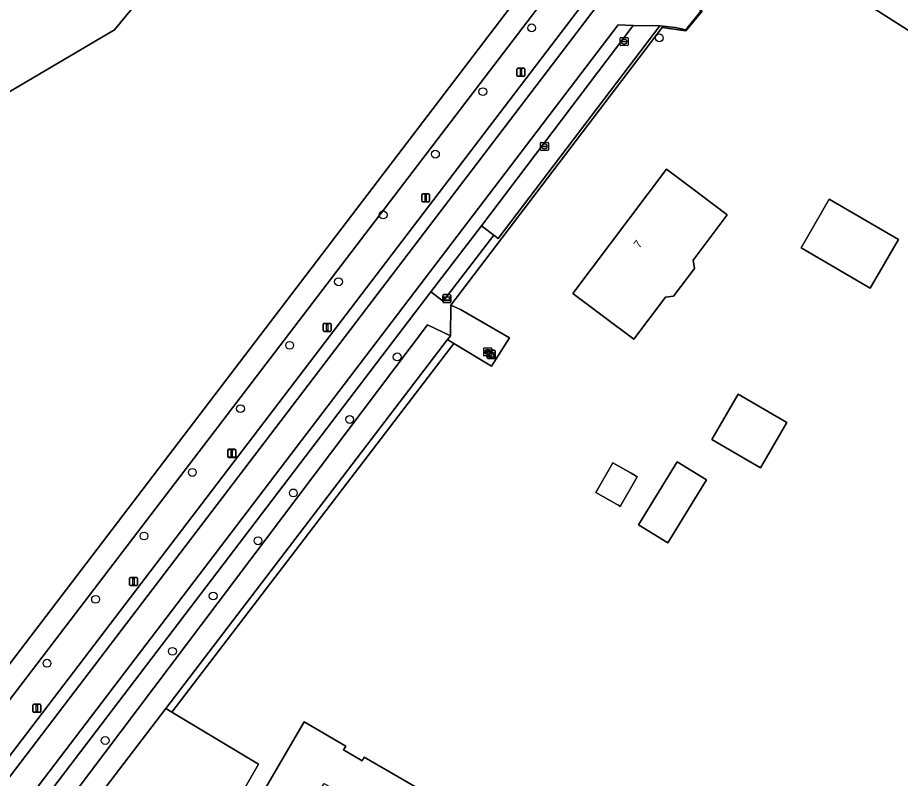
# Model space of a CAD drawing. Extents: x 156502 to 159075, y 384229 to 386100.
# Drawn here: x 157087.9 to 157198.2, y 385919.1 to 386014.1 of the extents above; entities that cross this region are included whole.
import ezdxf

# ---------------------------------------------------------------- set-up
doc = ezdxf.new("R2010")
doc.units = 0
for name, color, linetype in [('IMGEO_Berm_groen', 7, 'Continuous'), ('IMGEO_Berm_halfverhard', 7, 'Continuous'), ('IMGEO_Boom', 7, 'Continuous'), ('IMGEO_Bouwland', 7, 'Continuous'), ('IMGEO_Erf', 7, 'Continuous'), ('IMGEO_Gemengd_bos', 7, 'Continuous'), ('IMGEO_Greppel_droge_sloot', 7, 'Continuous'), ('IMGEO_Groenvoorziening', 7, 'Continuous'), ('IMGEO_Haag', 7, 'Continuous'), ('IMGEO_Hek', 7, 'Continuous'), ('IMGEO_Kast', 7, 'Continuous'), ('IMGEO_Kolk', 7, 'Continuous'), ('IMGEO_Lichtmast', 7, 'Continuous'), ('IMGEO_Pand', 7, 'Continuous'), ('IMGEO_Pand_nummerreeks', 7, 'Continuous'), ('IMGEO_Parkeervlak_open', 7, 'Continuous'), ('IMGEO_Rijbaan_lokaal_gesloten', 7, 'Continuous'), ('IMGEO_Rijbaan_lokaal_halfverhard', 7, 'Continuous'), ('IMGEO_Verklikker', 7, 'Continuous')]:
    doc.layers.add(name, color=color, linetype=linetype)

msp = doc.modelspace()

# ---------------------------------------------------------------- linework, layer by layer
at = {"layer": 'IMGEO_Berm_groen'}
for points in [[(157188.57, 386055.16), (157184.91, 386057.23), (157021.92, 385843.89)], [(157027.78, 385843.92), (157039.62, 385859.74), (157076.32, 385908.03), (157188.57, 386055.16)]]:
    msp.add_lwpolyline(points, dxfattribs=at)
at = {"layer": 'IMGEO_Berm_halfverhard'}
msp.add_lwpolyline([(157028.97, 385842.84), (157041.69, 385859.8), (157077.66, 385907.17), (157189.92, 386054.4), (157188.57, 386055.16), (157076.32, 385908.03), (157039.62, 385859.74), (157027.78, 385843.92), (157027.69, 385843.8)], dxfattribs=at)
at = {"layer": 'IMGEO_Boom'}
for centre in [(157152.16, 386012.81), (157168.11, 386011.56), (157146.06, 386004.85), (157140.13, 385997.05), (157133.6, 385989.46), (157128.03, 385981.12), (157121.92, 385973.18), (157135.36, 385971.74), (157115.78, 385965.28), (157129.42, 385963.93), (157109.76, 385957.32), (157122.38, 385954.76), (157103.73, 385949.39), (157117.97, 385948.79), (157097.68, 385941.48), (157112.37, 385941.9), (157107.28, 385934.98), (157091.61, 385933.5), (157098.88, 385923.85)]:
    msp.add_circle(centre, 0.489, dxfattribs=at)
at = {"layer": 'IMGEO_Bouwland'}
msp.add_lwpolyline([(156974.12, 385919.07), (156981.06, 385927.49), (156999.47, 385912.63), (157001.34, 385911.38), (157012.48, 385911.49), (157024.38, 385917.58), (157049.78, 385948.53), (157048.46, 385958.06), (157066.45, 385980.33), (157069.73, 385990.23), (157074.43, 385999.04), (157083.49, 386002.82), (157100.05, 386012.56), (157112.23, 386027.38), (157119.9, 386031.61), (157141.86, 386060.72), (157107.64, 386042.33), (157071.8, 386022.27), (157033.35, 385999.52), (156996.42, 385971.47), (156962.21, 385939.8), (156965.94, 385930.62)], close=True, dxfattribs=at)
at = {"layer": 'IMGEO_Erf'}
for points in [[(157291.8, 385905.79), (157257.61, 385922.62), (157240.01, 385933.44), (157265.45, 385970.38), (157218.89, 386000), (157178.39, 386025.76), (157172.11, 386017.58), (157173.41, 386014.87), (157171.43, 386012.44), (157168.45, 386012.84), (157142.06, 385978.18), (157143.26, 385977.64), (157149.37, 385974.1), (157147.13, 385970.6), (157142.45, 385973.43), (157107.2, 385927.4), (157118.02, 385920.91), (157113.03, 385912.2)], [(157116.59, 385913.9), (157123.72, 385926.17), (157128.92, 385923.15), (157128.64, 385922.69), (157130.99, 385921.32), (157131.25, 385921.79), (157140.51, 385916.41)]]:
    msp.add_lwpolyline(points, dxfattribs=at)
for points in [[(157172.31, 385983.8), (157172.48, 385982.77), (157169.89, 385979.33), (157168.86, 385979.21), (157164.9, 385973.95), (157161.31, 385976.66), (157157.31, 385979.67), (157168.99, 385995.17), (157172.98, 385992.16), (157176.57, 385989.46)], [(157194.44, 385980.33), (157185.8, 385985.36), (157189.32, 385991.41), (157197.96, 385986.39)], [(157174.65, 385961.41), (157177.94, 385967.1), (157184.02, 385963.57), (157180.72, 385957.89)], [(157163.23, 385953.08), (157162.99, 385953.22), (157162.77, 385953.34), (157160.18, 385954.81), (157162.28, 385958.52), (157164.57, 385957.22), (157165.09, 385956.93), (157165.33, 385956.79)], [(157170.33, 385958.65), (157173.99, 385956.41), (157169.15, 385948.52), (157165.5, 385950.76)]]:
    msp.add_lwpolyline(points, close=True, dxfattribs=at)
at = {"layer": 'IMGEO_Gemengd_bos'}
msp.add_lwpolyline([(157202.77, 386052.01), (157197.24, 386050.03), (157178.39, 386025.76), (157218.89, 386000), (157265.45, 385970.38), (157240.01, 385933.44), (157257.61, 385922.62), (157291.8, 385905.79), (157297.29, 385911.48), (157341.88, 385885.73), (157336.95, 385876.45), (157374.53, 385855.11), (157371.55, 385848.55), (157374.24, 385846.99), (157374.53, 385846.95), (157374.77, 385847.13), (157419.09, 385923.89)], dxfattribs=at)
at = {"layer": 'IMGEO_Greppel_droge_sloot'}
msp.add_lwpolyline([(157141.65, 385973.91), (157142.01, 385974.37), (157139.13, 385975.73), (157092.85, 385914.37), (157093.86, 385913.53), (157094.87, 385912.7), (157106.47, 385927.87)], close=True, dxfattribs=at)
at = {"layer": 'IMGEO_Groenvoorziening'}
for points in [[(157021.92, 385843.89), (157184.91, 386057.23), (157182.47, 386058.61), (157155.61, 386073.82), (157152.8, 386073.94)], [(156974.12, 385919.07), (156965.94, 385930.62), (156962.21, 385939.8), (156996.42, 385971.47), (157033.35, 385999.52), (157071.8, 386022.27), (157107.64, 386042.33), (157141.86, 386060.72), (157157.67, 386069.21), (157180.63, 386056.21), (157071.09, 385912.7)], [(157168.45, 386012.84), (157168.58, 386013.01), (157168.15, 386013.05), (157147.95, 385986.53), (157147.42, 385986.93), (157141.08, 385978.7), (157139.56, 385979.86), (157091.66, 385917.04), (157090.82, 385915.95)], [(157092.52, 385905), (157095.28, 385903.36), (157097.84, 385907.57), (157092.8, 385910.63), (157093.2, 385911.32), (157094.87, 385912.7), (157093.86, 385913.53), (157092.85, 385914.37), (157139.13, 385975.73), (157142.01, 385974.37), (157142.06, 385978.18), (157168.45, 386012.84)]]:
    msp.add_lwpolyline(points, dxfattribs=at)
for points in [[(157180.63, 386056.21), (157157.67, 386069.21), (157141.86, 386060.72), (157119.9, 386031.61), (157112.23, 386027.38), (157100.05, 386012.56), (157083.49, 386002.82), (157074.43, 385999.04), (157069.73, 385990.23), (157066.45, 385980.33), (157048.46, 385958.06), (157049.78, 385948.53), (157024.38, 385917.58), (157012.48, 385911.49), (157001.34, 385911.38), (156999.47, 385912.63), (156989.3, 385898.64), (156990.12, 385896.68), (157010.16, 385862.56), (157019, 385846.69), (157019.84, 385845.79), (157029.05, 385857.93), (157071.09, 385912.7)], [(157168.45, 386012.84), (157171.43, 386012.44), (157173.41, 386014.87), (157172.11, 386017.58), (157171.96, 386017.39), (157172.19, 386016.84), (157173.28, 386014.88), (157171.41, 386012.56), (157170.09, 386012.85), (157168.58, 386013.01)], [(157147.42, 385986.93), (157145.87, 385988.12), (157139.56, 385979.86), (157141.08, 385978.7)], [(157142.01, 385974.37), (157141.65, 385973.91), (157142.45, 385973.43), (157147.13, 385970.6), (157149.37, 385974.1), (157143.26, 385977.64), (157142.06, 385978.18)], [(157142.45, 385973.43), (157141.65, 385973.91), (157106.47, 385927.87), (157107.2, 385927.4)], [(157112.19, 385911.06), (157112.62, 385911.8), (157125.68, 385904.13), (157125.95, 385904.61), (157113.03, 385912.2), (157118.02, 385920.91), (157107.2, 385927.4), (157106.47, 385927.87), (157094.87, 385912.7), (157093.2, 385911.32), (157119.85, 385895.68), (157124.47, 385903.81)]]:
    msp.add_lwpolyline(points, close=True, dxfattribs=at)
at = {"layer": 'IMGEO_Haag'}
msp.add_lwpolyline([(157147.42, 385986.93), (157145.87, 385988.12), (157139.56, 385979.86), (157141.08, 385978.7)], close=True, dxfattribs=at)
at = {"layer": 'IMGEO_Hek'}
for points in [[(157178.39, 386025.76), (157218.89, 386000), (157265.45, 385970.38), (157240.01, 385933.44)], [(157171.43, 386012.44), (157173.41, 386014.87)], [(157142.06, 385978.18), (157168.45, 386012.84), (157171.43, 386012.44)], [(157143.26, 385977.64), (157142.06, 385978.18)], [(157143.26, 385977.64), (157149.37, 385974.1)], [(157142.45, 385973.43), (157147.13, 385970.6), (157149.37, 385974.1)], [(157118.02, 385920.91), (157107.2, 385927.4), (157142.45, 385973.43)], [(157125.95, 385904.61), (157113.03, 385912.2), (157118.02, 385920.91)]]:
    msp.add_lwpolyline(points, dxfattribs=at)
at = {"layer": 'IMGEO_Kast'}
for p, q in [((157146.67, 385972.56), (157147.51, 385972.56)), ((157147.51, 385972.56), (157146.67, 385972.56)), ((157146.59, 385971.64), (157146.59, 385972.48)), ((157146.59, 385972.48), (157146.59, 385971.64)), ((157147.52, 385971.56), (157146.68, 385971.56)), ((157146.68, 385971.56), (157147.52, 385971.56)), ((157147.59, 385972.49), (157147.59, 385971.65)), ((157147.59, 385971.65), (157147.59, 385972.49))]:
    msp.add_line(p, q, dxfattribs=at)
for points in [[(157146.79, 385972.35), (157147.39, 385972.35), (157147.39, 385972.27), (157146.79, 385972.27), (157146.79, 385972.35)], [(157146.79, 385972.18), (157147.39, 385972.18), (157147.39, 385971.69), (157146.79, 385971.69), (157146.79, 385972.18)]]:
    msp.add_lwpolyline(points, dxfattribs=at)
msp.add_circle((157146.87, 385972.02), 0.0377, dxfattribs=at)
for centre, start, end in [((157146.67, 385972.48), 92.4484, 184.2845), ((157146.67, 385972.48), 92.4484, 184.2845), ((157147.51, 385972.48), 2.4484, 94.2845), ((157147.51, 385972.48), 2.4484, 94.2845), ((157146.67, 385971.64), 182.4484, 274.2845), ((157146.67, 385971.64), 182.4484, 274.2845), ((157147.51, 385971.64), 272.4484, 4.2845), ((157147.51, 385971.64), 272.4484, 4.2845)]:
    msp.add_arc(centre, 0.0779, start, end, dxfattribs=at)
at = {"layer": 'IMGEO_Kolk'}
for p, q in [((157163.2, 386010.68), (157163.2, 386011.53)), ((157163.28, 386011.6), (157164.13, 386011.6)), ((157163.46, 386011.1), (157163.46, 386011.11)), ((157163.5, 386011.15), (157163.9, 386011.15)), ((157163.69, 386011.38), (157163.71, 386011.38)), ((157163.94, 386011.11), (157163.94, 386011.1)), ((157164.2, 386011.53), (157164.2, 386010.68)), ((157164.13, 386010.6), (157163.28, 386010.6)), ((157163.9, 386011.06), (157163.5, 386011.06)), ((157163.71, 386010.82), (157163.69, 386010.82)), ((157153.25, 385997.58), (157153.25, 385998.43)), ((157153.33, 385998.51), (157154.18, 385998.51)), ((157153.51, 385998), (157153.51, 385998.01)), ((157153.55, 385998.05), (157153.95, 385998.05)), ((157153.95, 385997.96), (157153.55, 385997.96)), ((157153.74, 385998.29), (157153.77, 385998.29)), ((157154, 385998.01), (157154, 385998)), ((157154.25, 385998.43), (157154.25, 385997.58)), ((157154.18, 385997.51), (157153.33, 385997.51)), ((157153.76, 385997.73), (157153.74, 385997.73)), ((157146.16, 385971.94), (157146.16, 385972.8)), ((157146.23, 385972.87), (157147.08, 385972.87)), ((157146.65, 385972.65), (157146.67, 385972.65)), ((157147.16, 385972.8), (157147.16, 385971.94)), ((157147.08, 385971.87), (157146.23, 385971.87)), ((157146.42, 385972.36), (157146.42, 385972.38)), ((157146.46, 385972.41), (157146.86, 385972.41)), ((157146.85, 385972.33), (157146.46, 385972.33)), ((157146.67, 385972.09), (157146.64, 385972.09)), ((157146.9, 385972.38), (157146.9, 385972.36))]:
    msp.add_line(p, q, dxfattribs=at)
for points in [[(157163.2, 386010.68), (157163.2, 386011.53)], [(157163.28, 386011.6), (157164.13, 386011.6)], [(157164.2, 386011.53), (157164.2, 386010.68)], [(157164.13, 386010.6), (157163.28, 386010.6)], [(157153.25, 385997.58), (157153.25, 385998.43)], [(157153.33, 385998.51), (157154.18, 385998.51)], [(157154.25, 385998.43), (157154.25, 385997.58)], [(157154.18, 385997.51), (157153.33, 385997.51)], [(157146.16, 385971.94), (157146.16, 385972.8)], [(157146.23, 385972.87), (157147.08, 385972.87)], [(157147.16, 385972.8), (157147.16, 385971.94)], [(157147.08, 385971.87), (157146.23, 385971.87)]]:
    msp.add_lwpolyline(points, dxfattribs=at)
for centre, radius, start, end in [((157163.28, 386011.53), 0.0765, 91.552, 178.448), ((157163.28, 386011.53), 0.0765, 91.552, 178.448), ((157163.5, 386011.11), 0.0403, 85.8775, 175.7526), ((157163.91, 386011.11), 0.0386, 1.7309, 96.639), ((157164.13, 386011.53), 0.0765, 1.552, 88.448), ((157164.13, 386011.53), 0.0765, 1.552, 88.448), ((157163.28, 386010.68), 0.0765, 181.552, 268.448), ((157163.28, 386010.68), 0.0765, 181.552, 268.448), ((157163.5, 386011.1), 0.0366, 178.938, 274.7102), ((157163.9, 386011.1), 0.043, 264.8664, 352.4533), ((157164.13, 386010.68), 0.0765, 271.552, 358.448), ((157164.13, 386010.68), 0.0765, 271.552, 358.448), ((157153.33, 385998.43), 0.0765, 91.552, 178.448), ((157153.33, 385998.43), 0.0765, 91.552, 178.448), ((157153.55, 385998.01), 0.0403, 85.8775, 175.7526), ((157153.55, 385998), 0.0366, 178.938, 274.7102), ((157153.96, 385998.01), 0.0386, 1.7309, 96.639), ((157153.95, 385998.01), 0.043, 264.8664, 352.4533), ((157154.18, 385998.43), 0.0765, 1.552, 88.448), ((157154.18, 385998.43), 0.0765, 1.552, 88.448), ((157153.33, 385997.58), 0.0765, 181.552, 268.448), ((157153.33, 385997.58), 0.0765, 181.552, 268.448), ((157154.18, 385997.58), 0.0765, 271.552, 358.448), ((157154.18, 385997.58), 0.0765, 271.552, 358.448), ((157146.23, 385972.79), 0.0765, 91.552, 178.448), ((157146.23, 385972.79), 0.0765, 91.552, 178.448), ((157147.08, 385972.79), 0.0765, 1.552, 88.448), ((157147.08, 385972.79), 0.0765, 1.552, 88.448), ((157146.23, 385971.94), 0.0765, 181.552, 268.448), ((157146.23, 385971.94), 0.0765, 181.552, 268.448), ((157146.46, 385972.37), 0.0403, 85.8775, 175.7526), ((157146.45, 385972.36), 0.0366, 178.938, 274.7102), ((157146.86, 385972.37), 0.043, 264.8664, 352.4533), ((157146.86, 385972.37), 0.0386, 1.7309, 96.639), ((157147.08, 385971.94), 0.0765, 271.552, 358.448), ((157147.08, 385971.94), 0.0765, 271.552, 358.448)]:
    msp.add_arc(centre, radius, start, end, dxfattribs=at)
for centre, major_axis, ratio, start_param, end_param in [((157163.69, 386011.1), (-0.387, 0.002), 0.722429, 4.712389, 7.853982), ((157163.71, 386011.1), (-0.39, 0.002), 0.717154, 1.570796, 4.712389), ((157153.74, 385998.01), (-0.387, 0.002), 0.722429, 4.712389, 7.853982), ((157153.76, 385998.01), (-0.39, 0.002), 0.717154, 1.570796, 4.712389), ((157146.64, 385972.37), (-0.387, 0.002), 0.722429, 4.712389, 7.853982), ((157146.67, 385972.37), (-0.39, 0.002), 0.717154, 1.570796, 4.712389)]:
    msp.add_ellipse(centre, major_axis=major_axis, ratio=ratio, start_param=start_param, end_param=end_param, dxfattribs=at)
at = {"layer": 'IMGEO_Lichtmast'}
for p, q in [((157150.32, 386006.87), (157150.32, 386007.67)), ((157150.32, 386007.67), (157150.32, 386006.87)), ((157150.42, 386007.77), (157151.2, 386007.77)), ((157151.2, 386007.77), (157150.42, 386007.77)), ((157151.2, 386006.77), (157150.42, 386006.77)), ((157150.42, 386006.77), (157151.2, 386006.77)), ((157151.3, 386007.67), (157151.3, 386006.87)), ((157151.3, 386006.87), (157151.3, 386007.67)), ((157138.42, 385991.2), (157138.42, 385992)), ((157138.42, 385992), (157138.42, 385991.2)), ((157138.52, 385992.1), (157139.31, 385992.1)), ((157139.31, 385992.1), (157138.52, 385992.1)), ((157139.41, 385992), (157139.41, 385991.2)), ((157139.41, 385991.2), (157139.41, 385992)), ((157139.31, 385991.1), (157138.52, 385991.1)), ((157138.52, 385991.1), (157139.31, 385991.1)), ((157126.12, 385975.03), (157126.12, 385975.83)), ((157126.12, 385975.83), (157126.12, 385975.03)), ((157126.22, 385975.93), (157127.01, 385975.93)), ((157127.01, 385975.93), (157126.22, 385975.93)), ((157127.11, 385975.83), (157127.11, 385975.03)), ((157127.11, 385975.03), (157127.11, 385975.83)), ((157127.01, 385974.93), (157126.22, 385974.93)), ((157126.22, 385974.93), (157127.01, 385974.93)), ((157114.19, 385959.33), (157114.19, 385960.13)), ((157114.19, 385960.13), (157114.19, 385959.33)), ((157114.19, 385959.28), (157114.19, 385960.08)), ((157114.19, 385960.08), (157114.19, 385959.28)), ((157114.29, 385960.23), (157115.08, 385960.23)), ((157115.08, 385960.23), (157114.29, 385960.23)), ((157114.29, 385960.18), (157115.08, 385960.18)), ((157115.08, 385960.18), (157114.29, 385960.18)), ((157115.18, 385960.13), (157115.18, 385959.33)), ((157115.18, 385959.33), (157115.18, 385960.13)), ((157115.18, 385960.08), (157115.18, 385959.28)), ((157115.18, 385959.28), (157115.18, 385960.08)), ((157115.08, 385959.23), (157114.29, 385959.23)), ((157114.29, 385959.23), (157115.08, 385959.23)), ((157115.08, 385959.18), (157114.29, 385959.18)), ((157114.29, 385959.18), (157115.08, 385959.18)), ((157101.93, 385943.3), (157101.93, 385944.1)), ((157101.93, 385944.1), (157101.93, 385943.3)), ((157102.03, 385944.2), (157102.82, 385944.2)), ((157102.82, 385944.2), (157102.03, 385944.2)), ((157102.92, 385944.1), (157102.92, 385943.3)), ((157102.92, 385943.3), (157102.92, 385944.1)), ((157102.82, 385943.2), (157102.03, 385943.2)), ((157102.03, 385943.2), (157102.82, 385943.2)), ((157089.85, 385927.48), (157089.85, 385928.28)), ((157089.85, 385928.28), (157089.85, 385927.48)), ((157089.95, 385928.38), (157090.74, 385928.38)), ((157090.74, 385928.38), (157089.95, 385928.38)), ((157090.74, 385927.38), (157089.95, 385927.38)), ((157089.95, 385927.38), (157090.74, 385927.38)), ((157090.84, 385928.28), (157090.84, 385927.48)), ((157090.84, 385927.48), (157090.84, 385928.28))]:
    msp.add_line(p, q, dxfattribs=at)
for points in [[(157150.74, 386007.65), (157150.89, 386007.65), (157150.89, 386006.9), (157150.74, 386006.9), (157150.74, 386007.65)], [(157138.84, 385991.98), (157138.99, 385991.98), (157138.99, 385991.23), (157138.84, 385991.23), (157138.84, 385991.98)], [(157126.54, 385975.8), (157126.69, 385975.8), (157126.69, 385975.05), (157126.54, 385975.05), (157126.54, 385975.8)], [(157114.61, 385960.1), (157114.76, 385960.1), (157114.76, 385959.35), (157114.61, 385959.35), (157114.61, 385960.1)], [(157114.61, 385960.05), (157114.76, 385960.05), (157114.76, 385959.3), (157114.61, 385959.3), (157114.61, 385960.05)], [(157102.35, 385944.08), (157102.5, 385944.08), (157102.5, 385943.33), (157102.35, 385943.33), (157102.35, 385944.08)], [(157090.27, 385928.25), (157090.42, 385928.25), (157090.42, 385927.5), (157090.27, 385927.5), (157090.27, 385928.25)]]:
    msp.add_lwpolyline(points, dxfattribs=at)
for centre, start, end in [((157150.42, 386007.67), 90, 180), ((157150.42, 386007.67), 90, 180), ((157150.42, 386006.87), 180, 270), ((157150.42, 386006.87), 180, 270), ((157151.2, 386007.67), 0, 90), ((157151.2, 386007.67), 360, 90), ((157151.2, 386006.87), 270, 0), ((157151.2, 386006.87), 270, 0), ((157138.52, 385992), 90, 180), ((157138.52, 385992), 90, 180), ((157139.31, 385992), 0, 90), ((157139.31, 385992), 360, 90), ((157138.52, 385991.2), 180, 270), ((157138.52, 385991.2), 180, 270), ((157139.31, 385991.2), 270, 0), ((157139.31, 385991.2), 270, 0), ((157126.22, 385975.83), 90, 180), ((157126.22, 385975.83), 90, 180), ((157127.01, 385975.83), 0, 90), ((157127.01, 385975.83), 360, 90), ((157126.22, 385975.03), 180, 270), ((157126.22, 385975.03), 180, 270), ((157127.01, 385975.03), 270, 0), ((157127.01, 385975.03), 270, 0), ((157114.29, 385960.13), 90, 180), ((157114.29, 385960.13), 90, 180), ((157114.29, 385960.08), 90, 180), ((157114.29, 385960.08), 90, 180), ((157114.29, 385959.33), 180, 270), ((157114.29, 385959.33), 180, 270), ((157115.08, 385960.13), 0, 90), ((157115.08, 385960.13), 360, 90), ((157115.08, 385960.08), 0, 90), ((157115.08, 385960.08), 360, 90), ((157115.08, 385959.33), 270, 0), ((157115.08, 385959.33), 270, 0), ((157114.29, 385959.28), 180, 270), ((157114.29, 385959.28), 180, 270), ((157115.08, 385959.28), 270, 0), ((157115.08, 385959.28), 270, 0), ((157102.03, 385944.1), 90, 180), ((157102.03, 385944.1), 90, 180), ((157102.82, 385944.1), 0, 90), ((157102.82, 385944.1), 360, 90), ((157102.03, 385943.3), 180, 270), ((157102.03, 385943.3), 180, 270), ((157102.82, 385943.3), 270, 0), ((157102.82, 385943.3), 270, 0), ((157089.95, 385928.28), 90, 180), ((157089.95, 385928.28), 90, 180), ((157089.95, 385927.48), 180, 270), ((157089.95, 385927.48), 180, 270), ((157090.74, 385928.28), 0, 90), ((157090.74, 385928.28), 360, 90), ((157090.74, 385927.48), 270, 0), ((157090.74, 385927.48), 270, 0)]:
    msp.add_arc(centre, 0.1, start, end, dxfattribs=at)
at = {"layer": 'IMGEO_Pand'}
for points in [[(157172.98, 385992.16), (157168.99, 385995.17), (157157.31, 385979.67), (157161.31, 385976.66), (157164.9, 385973.95), (157168.86, 385979.21), (157169.89, 385979.33), (157172.48, 385982.77), (157172.31, 385983.8), (157176.57, 385989.46)], [(157194.44, 385980.33), (157197.96, 385986.39), (157189.32, 385991.41), (157185.8, 385985.36)], [(157174.65, 385961.41), (157180.72, 385957.89), (157184.02, 385963.57), (157177.94, 385967.1)], [(157163.23, 385953.08), (157165.33, 385956.79), (157165.09, 385956.93), (157164.57, 385957.22), (157162.28, 385958.52), (157160.18, 385954.81), (157162.77, 385953.34), (157162.99, 385953.22)], [(157170.33, 385958.65), (157165.5, 385950.76), (157169.15, 385948.52), (157173.99, 385956.41)], [(157136.76, 385909.92), (157140.51, 385916.41), (157131.25, 385921.79), (157130.99, 385921.32), (157128.64, 385922.69), (157128.92, 385923.15), (157123.72, 385926.17), (157116.59, 385913.9), (157121.76, 385910.88), (157126.22, 385918.51), (157128.55, 385917.15), (157127.48, 385915.32), (157130.98, 385913.29)]]:
    msp.add_lwpolyline(points, close=True, dxfattribs=at)
at = {"layer": 'IMGEO_Parkeervlak_open'}
msp.add_lwpolyline([(157145.87, 385988.12), (157147.42, 385986.93), (157147.95, 385986.53), (157168.15, 386013.05), (157164.84, 386013.11)], close=True, dxfattribs=at)
at = {"layer": 'IMGEO_Rijbaan_lokaal_gesloten'}
for points in [[(157170.87, 386020.88), (157170.37, 386022.92), (157193.36, 386053.17), (157195.74, 386055.95), (157192.08, 386057.73), (157191.18, 386056.23), (157189.92, 386054.4), (157077.66, 385907.17), (157041.69, 385859.8), (157028.97, 385842.84), (157031.66, 385840.51)], [(157090.51, 385918.17), (157162.95, 386013.18), (157164.84, 386013.11), (157168.15, 386013.05), (157168.58, 386013.01), (157170.09, 386012.85), (157171.41, 386012.56), (157173.28, 386014.88), (157172.19, 386016.84), (157171.96, 386017.39), (157171.5, 386018.46)]]:
    msp.add_lwpolyline(points, dxfattribs=at)
at = {"layer": 'IMGEO_Rijbaan_lokaal_halfverhard'}
msp.add_lwpolyline([(157139.56, 385979.86), (157145.87, 385988.12), (157164.84, 386013.11), (157162.95, 386013.18), (157090.51, 385918.17), (157091.49, 385917.48), (157091.36, 385917.29), (157091.66, 385917.04)], close=True, dxfattribs=at)
at = {"layer": 'IMGEO_Verklikker'}
for p, q in [((157141.06, 385978.61), (157141.06, 385979.41)), ((157141.06, 385979.41), (157141.06, 385978.61)), ((157141.16, 385979.51), (157141.95, 385979.51)), ((157141.95, 385979.51), (157141.16, 385979.51)), ((157142.05, 385979.41), (157142.05, 385978.61)), ((157142.05, 385978.61), (157142.05, 385979.41)), ((157141.95, 385978.51), (157141.16, 385978.51)), ((157141.16, 385978.51), (157141.95, 385978.51))]:
    msp.add_line(p, q, dxfattribs=at)
for points in [[(157141.16, 385979.25), (157141.95, 385979.25), (157141.95, 385978.78), (157141.16, 385978.78), (157141.16, 385979.25)], [(157141.23, 385979.18), (157141.23, 385978.85), (157141.88, 385978.85), (157141.88, 385979.18), (157141.23, 385979.18)]]:
    msp.add_lwpolyline(points, dxfattribs=at)
for centre, start, end in [((157141.16, 385979.41), 90, 180), ((157141.16, 385979.41), 90, 180), ((157141.95, 385979.41), 0, 90), ((157141.95, 385979.41), 360, 90), ((157141.16, 385978.61), 180, 270), ((157141.16, 385978.61), 180, 270), ((157141.95, 385978.61), 270, 0), ((157141.95, 385978.61), 270, 0)]:
    msp.add_arc(centre, 0.1, start, end, dxfattribs=at)

# ---------------------------------------------------------------- texts
at = {"layer": 'IMGEO_Pand_nummerreeks'}
msp.add_text('7', height=1, rotation=53.0262, dxfattribs=at).set_placement((157165.6, 385985.23))

doc.saveas('drawing.dxf')
